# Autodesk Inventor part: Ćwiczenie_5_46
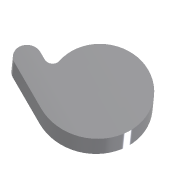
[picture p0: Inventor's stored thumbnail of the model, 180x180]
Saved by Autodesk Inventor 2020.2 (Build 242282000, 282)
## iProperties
Created: 2005-05
Part Number: Ćwiczenie_5_46
Document SubType Name: Modeling
Designer: F.Stasiak
Manufacturer: Standard
Standards Organization: Custom
Density: 1 g/cm^3
Material: Ogólny
Appearance: Aluminium — polerowane
Manager: www.cadconsulting.pl
Company: Fabian Stasiak CAD Consulting
Author: F.Stasiak
Subject: Zbiór ćwiczeń. Autodesk Inventor 2020. Kurs podstawowy
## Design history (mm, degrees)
sketch "Szkic1"
  geometry: L1 (3, 3)-(3, -3); L2 (0, 3)-(0, -3); L3 (-3, 3)-(3, 3); L4 (3, -3)-(-3, -3); L5 (-3, -3)-(-3, 3); L6 (3, 87)-(105, 87); L7 (105, 87)-(105, 47); L8 (105, 47)-(48.807, 47); A1 r 72 centre (-3, -3) between (-3, -75) and (48.807, 47); A2 r 78 centre (-3, 3) between (-81, 3) and (-3, -75); A3 r 84 centre (3, 3) between (3, 87) and (-81, 3); 2 further points
  constraints: 16 end point, 6 point on circle, 3 centre point, 3 midpoint, 3 parallel, 3 perpendicular, 3 tangent, 1 coincident, 1 horizontal
  dimensions: "d3" = 84 radius of A3; "d4" = 78 radius of A2; "d5" = 72 radius of A1; "d110" = 40 distance of L6.end L7.end; "d111" = 105 distance from line of L7 point (0, 0)
extrude "Wyciągnięcie proste1" new body sketch "Szkic1" stored distance "d8" = 40; taper "d9" = 0 deg
feature "Skorupa4" dims "d278" = 5
sketch "Szkic16"
  geometry: C1 r 20 at (0, 0) reference
hole "Otwór1" sketch "Szkic16" at (0, 0) diameter "d317" = 20; stored, may be unused: countersink angle "d321" = 90 deg, drill point angle "d323" = 118 deg; dims "d318" = 6, "d319" = 4, "d320" = 2, "d322" = 8
node "Bryła1"
node "Korpusy bryłowe"
node "Korpusy powierzchniowe"
fillet "Zaokrąglenie1" dims "d123" = 20
fillet "Zaokrąglenie2" dims "d114" = 12
fillet "Zaokrąglenie3" dims "d279" = 5
sketch "Szkic17"
  geometry: C1 r 27.5 at (85, 67); A1 r 20 centre (85, 67) between (85, 47) and (85, 87) reference
  constraints: 1 centre point, 1 coincident
  dimensions: "d396" = 55 diameter of C1
extrude "Wyciągnięcie proste2" join sketch "Szkic17" distance "d397" = 5; taper "d398" = 0 deg
sketch "Szkic18"
  geometry: L1 (-66.125, 87)-(-85, 87) reference; L2 (-85, 47)-(-71.913, 47) reference; A1 r 27.5 centre (-85, 67) between (-66.125, 87) and (-67.202, 46.036) reference; A2 r 12 centre (-71.913, 35) between (-67.202, 46.036) and (-71.913, 47) reference; A3 r 20 centre (-85, 67) between (-85, 87) and (-85, 47) reference
extrude "Wyciągnięcie proste3" join sketch "Szkic18" distance "d399" = 19; taper "d400" = 0 deg
sketch "Szkic19"
  geometry: C1 r 27.5 at (0, 0) reference; C2 r 15 at (0, 0)
  constraints: 1 centre point, 1 coincident
  dimensions: "d401" = 30 diameter of C2
extrude "Wyciągnięcie proste4" cut sketch "Szkic19" distance "d402" = 25; taper "d403" = 0 deg
sketch "Szkic10"
  geometry: C1 r 62.5 at (-6, 0); 1 further point
  constraints: 1 centre point
  dimensions: "d520" = 125 diameter of C1; "d521" = 6 distance of point (0, 0) C1.centre; "d522" = 0 vertical distance of C1.centre point (0, 0)
extrude "Wyciągnięcie proste5" join sketch "Szkic10" distance "d269" = 2; taper "d270" = 0 deg
sketch "Szkic14"
  geometry: C1 r 62.5 at (6, 0) reference; C2 r 67 at (6, 0)
  constraints: 1 centre point, 1 coincident
  dimensions: "d309" = 134 diameter of C2
extrude "Wyciągnięcie proste6" join sketch "Szkic14" stored distance "d310" = 13; taper "d311" = 0 deg
fillet "Zaokrąglenie4" dims "d313" = 2
sketch "Szkic15"
  geometry: C1 r 67 at (0, 0) reference; C2 r 57.5 at (0, 0)
  constraints: 1 centre point, 1 coincident
  dimensions: "d314" = 115 diameter of C2
extrude "Wyciągnięcie proste7" cut sketch "Szkic15" distance "d315" = 45; taper "d316" = 0 deg
sketch "Szkic11"
  geometry: C1 r 62.5 at (0, 0) reference; C2 r 40 at (0, 0); C3 r 35 at (0, 0)
  constraints: 2 centre point, 2 coincident
  dimensions: "d271" = 80 diameter of C2; "d272" = 5 radial gap between concentric circles of C2 C3
extrude "Wyciągnięcie proste8" join sketch "Szkic11" distance "d273" = 10; taper "d274" = 0 deg
sketch "Szkic12"
  geometry: C1 r 35 at (0, 0) reference; C2 r 20 at (0, 0)
  constraints: 1 centre point, 1 coincident
  dimensions: "d275" = 40 diameter of C2
extrude "Wyciągnięcie proste9" join sketch "Szkic12" distance "d276" = 20; taper "d277" = 0 deg
node "Pętla rzutowana3"
node "Pętla rzutowana4"
node "Pętla rzutowana5"
node "Pętla rzutowana6"
node "Pętla rzutowana7"
